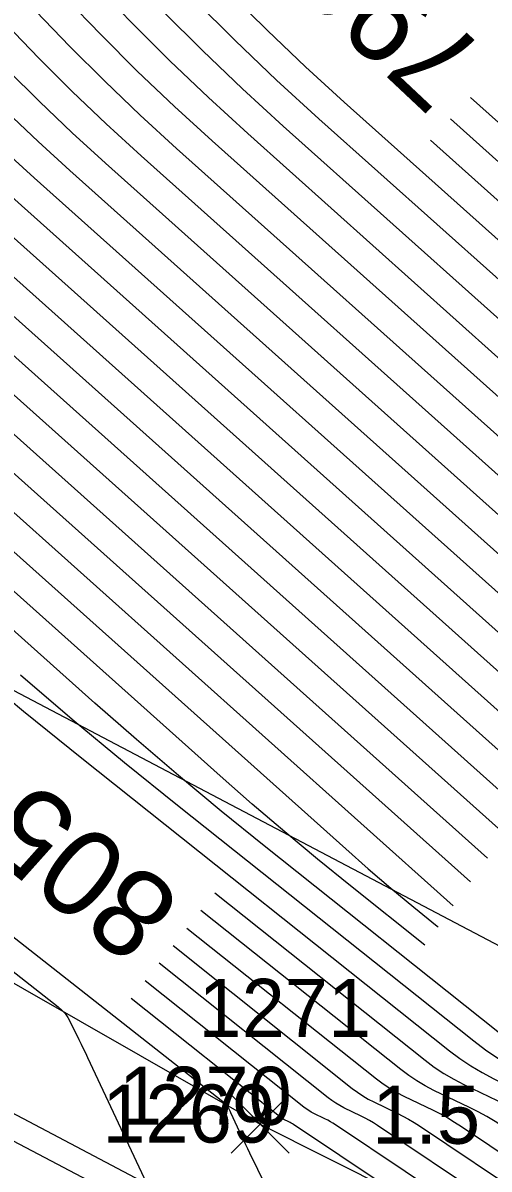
# Model space of a CAD drawing. Extents: x 1650836 to 1652450, y 332578 to 333908.
# Drawn here: x 1652115.54 to 1652131.6, y 332802.49 to 332841.97 of the extents above; entities that cross this region are included whole.
import ezdxf

# ---------------------------------------------------------------- set-up
doc = ezdxf.new("R2010")
doc.units = 0
for name, color, linetype in [('L_I', 7, 'Continuous'), ('L_TIC', 7, 'Continuous'), ('LAWA', 7, 'Continuous'), ('LELB', 7, 'Continuous'), ('LSOGCMA', 7, 'Continuous'), ('LSOGCMA_T', 7, 'Continuous'), ('LSOGCMI', 7, 'Continuous'), ('M_C', 7, 'Continuous'), ('P_I', 7, 'Continuous'), ('PET', 7, 'Continuous'), ('R_I', 7, 'Continuous'), ('RGR', 7, 'Continuous')]:
    doc.layers.add(name, color=color, linetype=linetype)

msp = doc.modelspace()

# ---------------------------------------------------------------- linework, layer by layer
at = {"layer": 'L_TIC'}
for points in [[(1652122.711, 332803.04), (1652124.711, 332805.04)], [(1652124.711, 332803.04), (1652122.711, 332805.04)]]:
    msp.add_lwpolyline(points, dxfattribs=at)
at = {"layer": 'LAWA'}
msp.add_lwpolyline([(1652408.76, 332665.713), (1652363.38, 332695.402), (1652324.46, 332714.991), (1652289.155, 332735.895), (1652253.497, 332747.946), (1652218.614, 332766.122), (1652198.198, 332775.017), (1652146.456, 332804.843), (1652136.841, 332807.592), (1652091.374, 332831.511), (1652057.601, 332848.138), (1652027.653, 332867.625)], dxfattribs=at)
at = {"layer": 'LELB'}
msp.add_lwpolyline([(1652023.441, 332859.649), (1652034.235, 332853.429), (1652052.246, 332842.357), (1652084.686, 332826.36), (1652123.711, 332804.04), (1652160.81, 332785.384), (1652195.281, 332767.897), (1652235.573, 332746.682), (1652255.289, 332735.81), (1652296.57, 332712.591), (1652348.8, 332686.345), (1652380.841, 332668.301), (1652404.073, 332656.539)], dxfattribs=at)
at = {"layer": 'LSOGCMA'}
for points in [[(1652138.017, 332819.621), (1652137.891, 332819.731), (1652136.751, 332820.729), (1652135.614, 332821.731), (1652134.48, 332822.736), (1652133.349, 332823.745), (1652118.384, 332837.134), (1652117.238, 332838.182), (1652116.115, 332839.254), (1652115.016, 332840.35)], [(1652158.91, 332820.766), (1652155.252, 332819.242), (1652155.009, 332819.169), (1652154.769, 332819.157), (1652154.535, 332819.205), (1652154.305, 332819.313), (1652153.393, 332819.865), (1652153.169, 332820.007), (1652152.951, 332820.159), (1652152.74, 332820.32), (1652152.536, 332820.491), (1652136.112, 332834.824), (1652135.221, 332835.604), (1652134.333, 332836.387), (1652133.447, 332837.172), (1652132.563, 332837.96), (1652130.956, 332839.398)], [(1652106.132, 332834.583), (1652130.953, 332812.376)], [(1652120.711, 332810.183), (1652126.885, 332805.269), (1652127.062, 332805.136), (1652127.245, 332805.014), (1652127.435, 332804.901), (1652127.632, 332804.8), (1652128.431, 332804.414), (1652128.629, 332804.314), (1652128.823, 332804.207), (1652129.014, 332804.094), (1652129.2, 332803.974), (1652144.4, 332793.781)]]:
    msp.add_lwpolyline(points, dxfattribs=at)
at = {"layer": 'LSOGCMI'}
for points in [[(1652073.002, 332867.027), (1652073.133, 332866.908), (1652073.312, 332866.76), (1652074.267, 332866.009), (1652074.487, 332865.835), (1652074.703, 332865.658), (1652074.918, 332865.478), (1652075.131, 332865.296), (1652096.386, 332846.822), (1652096.918, 332846.36), (1652097.448, 332845.898), (1652097.978, 332845.434), (1652098.508, 332844.97), (1652100.626, 332843.114), (1652101.149, 332842.643), (1652101.661, 332842.161), (1652102.161, 332841.666), (1652102.649, 332841.159), (1652105.751, 332837.856), (1652106.436, 332837.143), (1652107.137, 332836.444), (1652107.852, 332835.761), (1652108.582, 332835.093), (1652132.136, 332814.02)], [(1652114.69, 332851.463), (1652121.428, 332844.29), (1652122.682, 332842.984), (1652123.964, 332841.705), (1652125.273, 332840.455), (1652126.61, 332839.233), (1652132.011, 332834.4), (1652133.363, 332833.194), (1652134.719, 332831.992), (1652136.079, 332830.795), (1652137.442, 332829.601), (1652149.86, 332818.764), (1652150.175, 332818.501), (1652150.5, 332818.253), (1652150.835, 332818.018), (1652151.181, 332817.798), (1652152.587, 332816.948), (1652152.941, 332816.781), (1652153.303, 332816.707), (1652153.672, 332816.726), (1652154.047, 332816.838), (1652157.508, 332818.281)], [(1652156.715, 332817.316), (1652153.646, 332816.037), (1652153.226, 332815.912), (1652152.814, 332815.891), (1652152.41, 332815.973), (1652152.014, 332816.159), (1652150.444, 332817.11), (1652150.058, 332817.355), (1652149.683, 332817.617), (1652149.32, 332817.895), (1652148.968, 332818.188), (1652137.886, 332827.86), (1652136.365, 332829.192), (1652134.848, 332830.528), (1652133.336, 332831.868), (1652131.827, 332833.214), (1652125.735, 332838.664), (1652124.277, 332839.997), (1652122.849, 332841.361), (1652121.451, 332842.756), (1652120.082, 332844.181), (1652113.887, 332850.776)], [(1652155.922, 332816.352), (1652153.244, 332815.236), (1652152.78, 332815.098), (1652152.325, 332815.075), (1652151.879, 332815.165), (1652151.441, 332815.371), (1652149.707, 332816.421), (1652149.28, 332816.692), (1652148.866, 332816.982), (1652148.464, 332817.288), (1652148.076, 332817.613), (1652138.329, 332826.119), (1652136.651, 332827.588), (1652134.977, 332829.063), (1652133.308, 332830.542), (1652131.643, 332832.027), (1652124.51, 332838.409), (1652123.104, 332839.695), (1652121.727, 332841.01), (1652120.378, 332842.355), (1652119.059, 332843.73), (1652113.084, 332850.089)], [(1652155.918, 332815.432), (1652155.588, 332815.508), (1652155.128, 332815.388), (1652152.842, 332814.435), (1652152.335, 332814.284), (1652151.837, 332814.258), (1652151.348, 332814.358), (1652150.868, 332814.583), (1652148.97, 332815.732), (1652148.502, 332816.03), (1652148.049, 332816.346), (1652147.609, 332816.682), (1652147.184, 332817.037), (1652138.327, 332824.767), (1652136.713, 332826.179), (1652135.104, 332827.597), (1652133.5, 332829.019), (1652131.9, 332830.446), (1652123.285, 332838.154), (1652121.931, 332839.392), (1652120.604, 332840.659), (1652119.306, 332841.954), (1652118.035, 332843.278), (1652112.282, 332849.402)], [(1652111.479, 332848.715), (1652117.011, 332842.826), (1652118.233, 332841.553), (1652119.482, 332840.308), (1652120.757, 332839.09), (1652122.06, 332837.899), (1652132.262, 332828.771), (1652133.745, 332827.448), (1652135.232, 332826.13), (1652136.723, 332824.817), (1652138.218, 332823.508), (1652142.625, 332819.662)], [(1652110.676, 332848.028), (1652115.988, 332842.374), (1652117.161, 332841.152), (1652118.36, 332839.956), (1652119.584, 332838.787), (1652120.834, 332837.644), (1652132.624, 332827.096), (1652133.99, 332825.878), (1652135.359, 332824.664), (1652136.732, 332823.454), (1652138.109, 332822.249), (1652139.312, 332821.199)], [(1652138.664, 332820.41), (1652138, 332820.99), (1652136.742, 332822.092), (1652135.486, 332823.197), (1652134.235, 332824.307), (1652132.986, 332825.42), (1652119.609, 332837.389), (1652118.411, 332838.484), (1652117.237, 332839.605), (1652116.088, 332840.751), (1652114.964, 332841.922)], [(1652137.37, 332818.833), (1652136.76, 332819.367), (1652135.741, 332820.264), (1652134.725, 332821.165), (1652133.711, 332822.07), (1652117.159, 332836.879), (1652116.065, 332837.879), (1652114.993, 332838.903)], [(1652159.6, 332820.42), (1652154.851, 332818.44), (1652154.563, 332818.355), (1652154.281, 332818.34), (1652154.004, 332818.397), (1652153.732, 332818.524), (1652152.656, 332819.176), (1652152.391, 332819.344), (1652152.134, 332819.524), (1652151.885, 332819.714), (1652151.644, 332819.915), (1652136.555, 332833.083), (1652135.507, 332834.001), (1652134.462, 332834.922), (1652133.419, 332835.846), (1652132.379, 332836.773), (1652130.266, 332838.664)], [(1652129.576, 332837.93), (1652132.195, 332835.587), (1652133.391, 332834.52), (1652134.591, 332833.457), (1652135.793, 332832.398), (1652136.999, 332831.342), (1652150.752, 332819.34), (1652151.03, 332819.108), (1652151.317, 332818.888), (1652151.613, 332818.681), (1652151.919, 332818.487), (1652153.159, 332817.736), (1652153.473, 332817.589), (1652153.792, 332817.524), (1652154.117, 332817.541), (1652154.449, 332817.639), (1652158.301, 332819.245)], [(1652136.723, 332818.045), (1652135.868, 332818.798), (1652134.969, 332819.595), (1652134.073, 332820.394), (1652115.934, 332836.624), (1652114.891, 332837.577)], [(1652114.708, 332836.369), (1652134.435, 332818.719)], [(1652134.798, 332817.044), (1652113.483, 332836.114)], [(1652111.033, 332835.603), (1652135.522, 332813.693)], [(1652135.16, 332815.368), (1652112.258, 332835.858)], [(1652109.807, 332835.348), (1652134.141, 332813.577)], [(1652107.357, 332834.838), (1652131.545, 332813.198)], [(1652130.361, 332811.554), (1652104.907, 332834.328)], [(1652103.681, 332834.073), (1652126.657, 332813.517), (1652127.431, 332812.834), (1652128.214, 332812.164), (1652129.007, 332811.504), (1652129.81, 332810.856), (1652129.841, 332810.831)], [(1652135.555, 332805.168), (1652133.829, 332806.001), (1652133.322, 332806.263), (1652132.832, 332806.552), (1652132.358, 332806.869), (1652131.902, 332807.212), (1652123.847, 332813.623), (1652122.364, 332814.821), (1652120.899, 332816.039), (1652119.452, 332817.279), (1652118.022, 332818.54), (1652101.231, 332833.563)], [(1652129.388, 332810.202), (1652126.828, 332812.239), (1652125.686, 332813.162), (1652124.557, 332814.101), (1652123.441, 332815.057), (1652122.34, 332816.028), (1652102.456, 332833.818)], [(1652125.263, 332799.145), (1652123.359, 332803.037), (1652123.29, 332803.18), (1652123.22, 332803.324), (1652123.152, 332803.469), (1652123.084, 332803.613), (1652122.702, 332804.43), (1652122.69, 332804.456), (1652122.678, 332804.482), (1652122.665, 332804.508), (1652122.652, 332804.534), (1652122.602, 332804.638), (1652122.588, 332804.662), (1652122.571, 332804.685), (1652122.552, 332804.706), (1652122.531, 332804.725), (1652091.942, 332828.748)], [(1652092.233, 332827.334), (1652116.755, 332808.076), (1652116.881, 332807.965), (1652116.993, 332807.842), (1652117.09, 332807.707), (1652117.172, 332807.56), (1652117.472, 332806.949), (1652117.547, 332806.796), (1652117.621, 332806.643), (1652117.694, 332806.489), (1652117.766, 332806.335), (1652119.793, 332801.998)], [(1652113.581, 332819.911), (1652115.564, 332818.261), (1652117.571, 332816.639), (1652130.229, 332806.564), (1652130.593, 332806.291), (1652130.97, 332806.039), (1652131.36, 332805.809), (1652131.764, 332805.6), (1652133.406, 332804.808), (1652133.812, 332804.603), (1652134.211, 332804.384), (1652134.601, 332804.151), (1652134.984, 332803.904), (1652158.506, 332788.131)], [(1652157.026, 332790.075), (1652136.43, 332803.886), (1652135.998, 332804.165), (1652135.557, 332804.428), (1652135.108, 332804.675), (1652134.649, 332804.906), (1652132.797, 332805.8), (1652132.341, 332806.036), (1652131.901, 332806.296), (1652131.475, 332806.58), (1652131.065, 332806.888), (1652120.866, 332815.006), (1652119.043, 332816.479), (1652117.242, 332817.977), (1652115.462, 332819.502)], [(1652122.157, 332812), (1652129.393, 332806.24), (1652129.71, 332806.002), (1652130.039, 332805.783), (1652130.379, 332805.582), (1652130.731, 332805.4), (1652132.162, 332804.709), (1652132.516, 332804.53), (1652132.864, 332804.339), (1652133.204, 332804.136), (1652133.538, 332803.921), (1652160.33, 332785.956)], [(1652155.507, 332788.238), (1652132.092, 332803.939), (1652131.807, 332804.122), (1652131.517, 332804.295), (1652131.221, 332804.458), (1652130.919, 332804.611), (1652129.698, 332805.2), (1652129.398, 332805.355), (1652129.107, 332805.526), (1652128.827, 332805.714), (1652128.557, 332805.917), (1652121.675, 332811.395)], [(1652121.193, 332810.789), (1652127.721, 332805.593), (1652127.945, 332805.425), (1652128.176, 332805.27), (1652128.416, 332805.128), (1652128.665, 332805), (1652129.675, 332804.512), (1652129.925, 332804.386), (1652130.17, 332804.251), (1652130.41, 332804.108), (1652130.646, 332803.956), (1652149.851, 332791.078)], [(1652138.949, 332796.484), (1652127.754, 332803.991), (1652127.617, 332804.08), (1652127.477, 332804.163), (1652127.334, 332804.242), (1652127.188, 332804.315), (1652126.599, 332804.6), (1652126.454, 332804.674), (1652126.314, 332804.757), (1652126.179, 332804.847), (1652126.049, 332804.945), (1652120.229, 332809.578)], [(1652133.499, 332799.187), (1652126.308, 332804.009), (1652126.22, 332804.065), (1652126.13, 332804.119), (1652126.038, 332804.17), (1652125.944, 332804.217), (1652125.566, 332804.399), (1652125.473, 332804.448), (1652125.383, 332804.501), (1652125.296, 332804.559), (1652125.213, 332804.621), (1652119.747, 332808.972)], [(1652128.048, 332801.89), (1652124.862, 332804.026), (1652124.823, 332804.051), (1652124.783, 332804.075), (1652124.742, 332804.097), (1652124.701, 332804.118), (1652124.533, 332804.199), (1652124.492, 332804.221), (1652124.452, 332804.244), (1652124.414, 332804.27), (1652124.377, 332804.298), (1652119.265, 332808.367)]]:
    msp.add_lwpolyline(points, dxfattribs=at)
at = {"layer": 'PET'}
msp.add_lwpolyline([(1651782.185, 332994.087), (1651800.504, 332980.945), (1651823.969, 332965.234), (1651861.092, 332941.311), (1651895.497, 332920.881), (1651932.1, 332899.878), (1651964.344, 332882.546), (1651997.084, 332865.287), (1652030.302, 332847.665), (1652049.548, 332837.673), (1652081.974, 332820.953), (1652121.026, 332800.401), (1652157.819, 332781.161), (1652191.945, 332763.077), (1652232.596, 332742.33), (1652251.93, 332731.59), (1652295.202, 332708.727), (1652345.726, 332682.336), (1652379.152, 332664.868), (1652402.111, 332652.828)], dxfattribs=at)
at = {"layer": 'RGR'}
msp.add_lwpolyline([(1652023.441, 332859.649), (1652024.915, 332854.382), (1652030.806, 332848.332), (1652049.928, 332838.521), (1652082.838, 332821.514), (1652121.63, 332801.012), (1652157.949, 332781.905), (1652192.709, 332763.821), (1652232.753, 332742.853), (1652252.846, 332732.22), (1652295.713, 332710.152), (1652346.443, 332683.145), (1652379.801, 332666.008), (1652402.772, 332654.006)], dxfattribs=at)

# ---------------------------------------------------------------- texts
at = {"layer": 'L_I'}
msp.add_text('1271', height=2, dxfattribs=at).set_placement((1652121.586, 332807.04))
at = {"layer": 'LSOGCMA_T'}
for s, rotation, p in [('790', 136.7696, (1652131.613, 332840.89)), ('805', 141.4818, (1652121.118, 332811.776))]:
    msp.add_text(s, height=3, rotation=rotation, dxfattribs=at).set_placement(p)
at = {"layer": 'M_C'}
msp.add_text('1.5 INCH DIA. LEANING  OVER', height=2, dxfattribs=at).set_placement((1652127.57, 332803.36))
at = {"layer": 'P_I'}
msp.add_text('1269', height=2, dxfattribs=at).set_placement((1652118.278, 332803.401))
at = {"layer": 'R_I'}
msp.add_text('1270', height=2, dxfattribs=at).set_placement((1652118.851, 332804.012))

doc.saveas('drawing.dxf')
